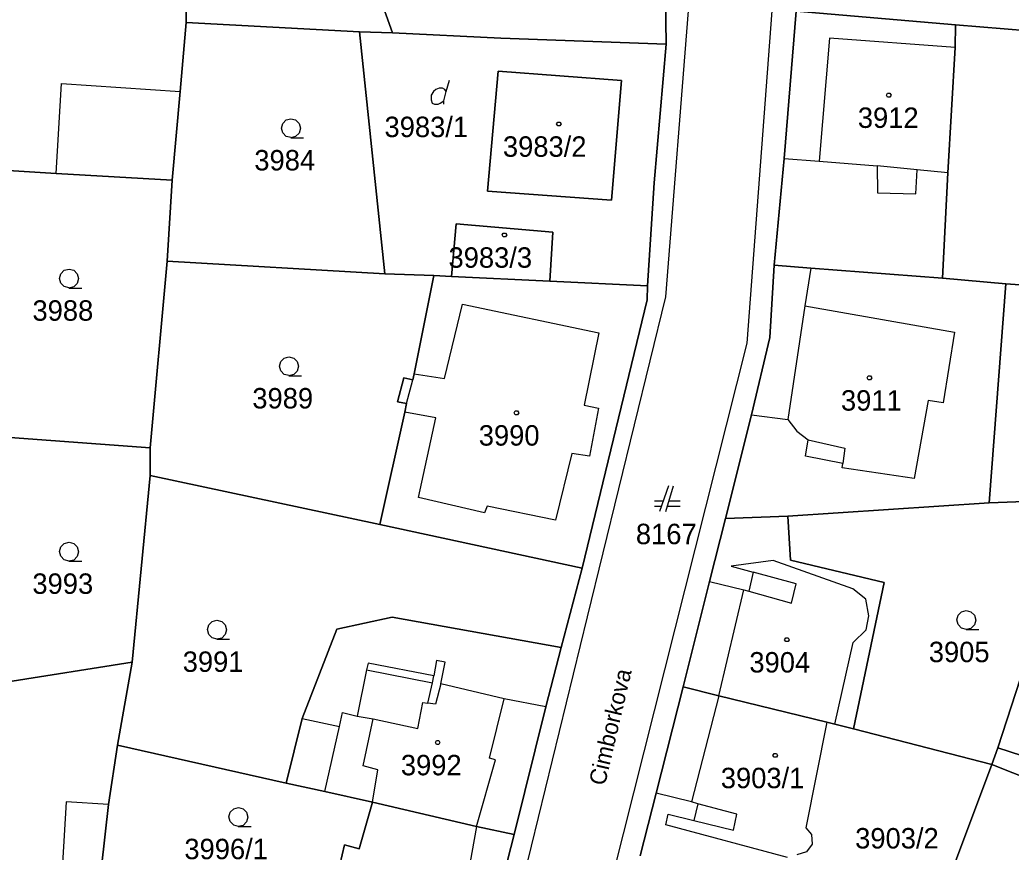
# Model space of a CAD drawing. Extents: x -263587 to -261993, y -1238795 to -1236748.
# Drawn here: x -262988.3 to -262910.7, y -1238143.7 to -1238078.5 of the extents above; entities that cross this region are included whole.
import ezdxf

# ---------------------------------------------------------------- set-up
doc = ezdxf.new("R2010")
doc.units = 0
doc.layers.add('Vrstva 1', color=7, linetype='Continuous')

msp = doc.modelspace()

# ---------------------------------------------------------------- linework, layer by layer
at = {"layer": 'Vrstva 1'}
for p, q in [((-262959.1, -1238079.5), (-262966.6, -1238058.58)), ((-262966.6, -1238058.58), (-262959.1, -1238079.5)), ((-262975.26, -1238076.52), (-262975.25, -1238078.69)), ((-262975.25, -1238078.69), (-262975.26, -1238076.52)), ((-262929.27, -1238076.08), (-262931.35, -1238103.82)), ((-262935.86, -1238076.77), (-262937.73, -1238100.17)), ((-262937.72, -1238076.78), (-262937.67, -1238080.39)), ((-262937.67, -1238080.39), (-262937.72, -1238076.78)), ((-262928.43, -1238089.35), (-262927.5, -1238077.82)), ((-262927.5, -1238077.82), (-262928.43, -1238089.35)), ((-262927.5, -1238077.82), (-262915, -1238078.87)), ((-262915, -1238078.87), (-262927.5, -1238077.82)), ((-262975.25, -1238078.69), (-262975.73, -1238084.11)), ((-262975.73, -1238084.11), (-262975.25, -1238078.69)), ((-262961.67, -1238079.42), (-262975.25, -1238078.69)), ((-262975.25, -1238078.69), (-262961.67, -1238079.42)), ((-262915, -1238078.87), (-262915.05, -1238080.66)), ((-262915.05, -1238080.66), (-262915, -1238078.87)), ((-262915, -1238078.87), (-262909.29, -1238079.36)), ((-262909.29, -1238079.36), (-262915, -1238078.87)), ((-262959.1, -1238079.5), (-262961.67, -1238079.42)), ((-262961.67, -1238079.42), (-262959.69, -1238098.38)), ((-262959.69, -1238098.38), (-262961.67, -1238079.42)), ((-262961.67, -1238079.42), (-262959.1, -1238079.5)), ((-262950.61, -1238079.92), (-262959.1, -1238079.5)), ((-262959.1, -1238079.5), (-262950.61, -1238079.92)), ((-262937.67, -1238080.39), (-262950.61, -1238079.92)), ((-262950.61, -1238079.92), (-262937.67, -1238080.39)), ((-262938.61, -1238091.24), (-262937.67, -1238080.39)), ((-262937.67, -1238080.39), (-262938.61, -1238091.24)), ((-262924.88, -1238079.92), (-262925.68, -1238089.56)), ((-262915.05, -1238080.66), (-262924.88, -1238079.92)), ((-262915.05, -1238080.66), (-262915.62, -1238090.47)), ((-262915.62, -1238090.47), (-262915.05, -1238080.66)), ((-262950.82, -1238082.51), (-262951.66, -1238091.9)), ((-262951.66, -1238091.9), (-262950.82, -1238082.51)), ((-262941.16, -1238083.23), (-262950.82, -1238082.51)), ((-262950.82, -1238082.51), (-262941.16, -1238083.23)), ((-262985.44, -1238090.51), (-262985, -1238083.47)), ((-262985, -1238083.47), (-262975.73, -1238084.11)), ((-262954.9, -1238084.11), (-262954.63, -1238083.21)), ((-262941.94, -1238092.6), (-262941.16, -1238083.23)), ((-262941.16, -1238083.23), (-262941.94, -1238092.6)), ((-262975.73, -1238084.11), (-262976.35, -1238091.04)), ((-262976.35, -1238091.04), (-262975.73, -1238084.11)), ((-262985.44, -1238090.51), (-263011.06, -1238089)), ((-263011.06, -1238089), (-262985.44, -1238090.51)), ((-262929.2, -1238097.69), (-262928.43, -1238089.35)), ((-262928.43, -1238089.35), (-262929.2, -1238097.69)), ((-262928.43, -1238089.35), (-262925.68, -1238089.56)), ((-262925.68, -1238089.56), (-262921.14, -1238089.92)), ((-262976.35, -1238091.04), (-262985.44, -1238090.51)), ((-262985.44, -1238090.51), (-262976.35, -1238091.04)), ((-262918.02, -1238090.23), (-262921.14, -1238089.92)), ((-262921.14, -1238089.92), (-262921.12, -1238092.03)), ((-262918.13, -1238092.12), (-262918.02, -1238090.23)), ((-262915.62, -1238090.47), (-262918.02, -1238090.23)), ((-262915.62, -1238090.47), (-262916.04, -1238098.72)), ((-262916.04, -1238098.72), (-262915.62, -1238090.47)), ((-262976.75, -1238097.38), (-262976.35, -1238091.04)), ((-262976.35, -1238091.04), (-262976.75, -1238097.38)), ((-262939.13, -1238099.33), (-262938.61, -1238091.24)), ((-262938.61, -1238091.24), (-262939.13, -1238099.33)), ((-262951.66, -1238091.9), (-262941.94, -1238092.6)), ((-262941.94, -1238092.6), (-262951.66, -1238091.9)), ((-262921.12, -1238092.03), (-262918.13, -1238092.12)), ((-262954.12, -1238094.47), (-262954.47, -1238098.59)), ((-262954.47, -1238098.59), (-262954.12, -1238094.47)), ((-262946.53, -1238095.12), (-262954.12, -1238094.47)), ((-262954.12, -1238094.47), (-262946.53, -1238095.12)), ((-262946.78, -1238098.96), (-262946.53, -1238095.12)), ((-262946.53, -1238095.12), (-262946.78, -1238098.96)), ((-262976.75, -1238097.38), (-262978.06, -1238112)), ((-262978.06, -1238112), (-262976.75, -1238097.38)), ((-262959.69, -1238098.38), (-262976.75, -1238097.38)), ((-262976.75, -1238097.38), (-262959.69, -1238098.38)), ((-262959.69, -1238098.38), (-262955.86, -1238098.52)), ((-262955.86, -1238098.52), (-262959.69, -1238098.38)), ((-262929.54, -1238103.37), (-262929.2, -1238097.69)), ((-262929.2, -1238097.69), (-262929.54, -1238103.37)), ((-262926.33, -1238097.93), (-262929.2, -1238097.69)), ((-262929.2, -1238097.69), (-262926.33, -1238097.93)), ((-262926.33, -1238097.93), (-262926.8, -1238100.88)), ((-262916.04, -1238098.72), (-262926.33, -1238097.93)), ((-262926.33, -1238097.93), (-262916.04, -1238098.72)), ((-262955.86, -1238098.52), (-262957.39, -1238106.22)), ((-262957.39, -1238106.22), (-262955.86, -1238098.52)), ((-262955.86, -1238098.52), (-262954.47, -1238098.59)), ((-262954.47, -1238098.59), (-262955.86, -1238098.52)), ((-262954.47, -1238098.59), (-262946.78, -1238098.96)), ((-262946.78, -1238098.96), (-262954.47, -1238098.59)), ((-262946.78, -1238098.96), (-262939.13, -1238099.33)), ((-262939.13, -1238099.33), (-262946.78, -1238098.96)), ((-262911.06, -1238099.15), (-262916.04, -1238098.72)), ((-262916.04, -1238098.72), (-262911.06, -1238099.15)), ((-262912.38, -1238116.3), (-262911.06, -1238099.15)), ((-262911.06, -1238099.15), (-262912.38, -1238116.3)), ((-262901.22, -1238099.95), (-262911.06, -1238099.15)), ((-262911.06, -1238099.15), (-262901.22, -1238099.95)), ((-262939.13, -1238099.33), (-262939.16, -1238100.42)), ((-262939.16, -1238100.42), (-262939.13, -1238099.33)), ((-262939.16, -1238100.42), (-262944.25, -1238121.44)), ((-262944.25, -1238121.44), (-262939.16, -1238100.42)), ((-262937.73, -1238100.17), (-262943.84, -1238125.24)), ((-262955.02, -1238106.58), (-262953.62, -1238100.76)), ((-262953.62, -1238100.76), (-262942.93, -1238102.99)), ((-262926.8, -1238100.88), (-262928.13, -1238109.79)), ((-262926.8, -1238100.88), (-262915.09, -1238102.94)), ((-262942.93, -1238102.99), (-262944.1, -1238108.65)), ((-262915.09, -1238102.94), (-262915.97, -1238108.49)), ((-262931.35, -1238103.82), (-262942.36, -1238147.46)), ((-262930.99, -1238109.43), (-262929.54, -1238103.37)), ((-262929.54, -1238103.37), (-262930.99, -1238109.43)), ((-262958.22, -1238106.51), (-262958.69, -1238108.39)), ((-262958.69, -1238108.39), (-262958.22, -1238106.51)), ((-262957.49, -1238106.68), (-262958.22, -1238106.51)), ((-262958.22, -1238106.51), (-262957.49, -1238106.68)), ((-262958, -1238108.54), (-262957.49, -1238106.68)), ((-262957.39, -1238106.22), (-262957.49, -1238106.68)), ((-262957.49, -1238106.68), (-262957.39, -1238106.22)), ((-262957.39, -1238106.22), (-262955.02, -1238106.58)), ((-262958.69, -1238108.39), (-262958, -1238108.54)), ((-262958, -1238108.54), (-262958.69, -1238108.39)), ((-262917.15, -1238108.29), (-262918.26, -1238114.41)), ((-262915.97, -1238108.49), (-262917.15, -1238108.29)), ((-262958.14, -1238109.2), (-262960.08, -1238118.02)), ((-262960.08, -1238118.02), (-262958.14, -1238109.2)), ((-262958, -1238108.54), (-262958.14, -1238109.2)), ((-262958.14, -1238109.2), (-262958, -1238108.54)), ((-262955.69, -1238109.65), (-262958.14, -1238109.2)), ((-262944.1, -1238108.65), (-262942.96, -1238108.9)), ((-262942.96, -1238108.9), (-262943.67, -1238112.66)), ((-262957.07, -1238115.9), (-262955.69, -1238109.65)), ((-262933.02, -1238117.55), (-262930.99, -1238109.43)), ((-262930.99, -1238109.43), (-262933.02, -1238117.55)), ((-262930.99, -1238109.43), (-262928.13, -1238109.79)), ((-262928.13, -1238109.79), (-262927.44, -1238110.7)), ((-262927.44, -1238110.7), (-262926.55, -1238111.38)), ((-262978.06, -1238112), (-262989.74, -1238111.14)), ((-262989.74, -1238111.14), (-262978.06, -1238112)), ((-262926.76, -1238112.66), (-262926.55, -1238111.38)), ((-262926.55, -1238111.38), (-262923.69, -1238112.02)), ((-262978.07, -1238114.16), (-262978.06, -1238112)), ((-262978.06, -1238112), (-262978.07, -1238114.16)), ((-262923.69, -1238112.02), (-262923.84, -1238113.23)), ((-262945.05, -1238112.45), (-262946.34, -1238117.66)), ((-262943.67, -1238112.66), (-262945.05, -1238112.45)), ((-262923.84, -1238113.23), (-262926.76, -1238112.66)), ((-262923.88, -1238113.56), (-262923.84, -1238113.23)), ((-262918.26, -1238114.41), (-262923.88, -1238113.56)), ((-262978.07, -1238114.16), (-262979.47, -1238128.79)), ((-262979.47, -1238128.79), (-262978.07, -1238114.16)), ((-262960.08, -1238118.02), (-262978.07, -1238114.16)), ((-262978.07, -1238114.16), (-262960.08, -1238118.02)), ((-262937.48, -1238114.98), (-262938.18, -1238116.98)), ((-262937.68, -1238116.98), (-262937.08, -1238114.98)), ((-262951.9, -1238117.1), (-262957.07, -1238115.9)), ((-262937.9, -1238116.18), (-262938.58, -1238116.18)), ((-262936.58, -1238116.18), (-262937.44, -1238116.18)), ((-262905.7, -1238116.06), (-262912.38, -1238116.3)), ((-262912.38, -1238116.3), (-262905.7, -1238116.06)), ((-262951.68, -1238116.56), (-262951.9, -1238117.1)), ((-262946.34, -1238117.66), (-262951.68, -1238116.56)), ((-262938.58, -1238116.58), (-262938.04, -1238116.58)), ((-262937.56, -1238116.58), (-262936.58, -1238116.58)), ((-262928.14, -1238117.35), (-262912.38, -1238116.3)), ((-262912.38, -1238116.3), (-262928.14, -1238117.35)), ((-262934.28, -1238122.46), (-262933.02, -1238117.55)), ((-262933.02, -1238117.55), (-262934.28, -1238122.46)), ((-262928.14, -1238117.35), (-262933.02, -1238117.55)), ((-262933.02, -1238117.55), (-262928.14, -1238117.35)), ((-262927.94, -1238120.79), (-262928.14, -1238117.35)), ((-262928.14, -1238117.35), (-262927.94, -1238120.79)), ((-262944.25, -1238121.44), (-262960.08, -1238118.02)), ((-262960.08, -1238118.02), (-262944.25, -1238121.44)), ((-262929.29, -1238120.82), (-262932.57, -1238121.28)), ((-262923.05, -1238123.04), (-262929.29, -1238120.82)), ((-262920.6, -1238122.56), (-262927.94, -1238120.79)), ((-262927.94, -1238120.79), (-262920.6, -1238122.56)), ((-262944.25, -1238121.44), (-262945.89, -1238127.64)), ((-262945.89, -1238127.64), (-262944.25, -1238121.44)), ((-262932.57, -1238121.28), (-262930.86, -1238121.74)), ((-262936.34, -1238130.73), (-262934.28, -1238122.46)), ((-262934.28, -1238122.46), (-262936.34, -1238130.73)), ((-262934.28, -1238122.46), (-262931.59, -1238123.12)), ((-262930.86, -1238121.74), (-262931.19, -1238123.22)), ((-262927.49, -1238122.65), (-262930.86, -1238121.74)), ((-262933.54, -1238131.42), (-262931.59, -1238123.12)), ((-262931.59, -1238123.12), (-262931.19, -1238123.22)), ((-262931.19, -1238123.22), (-262927.86, -1238124.18)), ((-262927.86, -1238124.18), (-262927.49, -1238122.65)), ((-262922.04, -1238123.86), (-262923.05, -1238123.04)), ((-262923.01, -1238134.01), (-262920.6, -1238122.56)), ((-262920.6, -1238122.56), (-262923.01, -1238134.01)), ((-262921.79, -1238125.16), (-262922.04, -1238123.86)), ((-262911.7, -1238135.5), (-262907.9, -1238123.78)), ((-262907.9, -1238123.78), (-262911.7, -1238135.5)), ((-262963.45, -1238126.21), (-262959.12, -1238125.26)), ((-262959.12, -1238125.26), (-262963.45, -1238126.21)), ((-262959.12, -1238125.26), (-262945.89, -1238127.64)), ((-262945.89, -1238127.64), (-262959.12, -1238125.26)), ((-262943.84, -1238125.24), (-262949.77, -1238149.44)), ((-262922.01, -1238126.27), (-262921.79, -1238125.16)), ((-262966.16, -1238133.2), (-262963.45, -1238126.21)), ((-262963.45, -1238126.21), (-262966.16, -1238133.2)), ((-262923.03, -1238127.25), (-262922.01, -1238126.27)), ((-262945.89, -1238127.64), (-262947.09, -1238132.29)), ((-262947.09, -1238132.29), (-262945.89, -1238127.64)), ((-262924.45, -1238133.64), (-262923.03, -1238127.25)), ((-262955.64, -1238128.67), (-262955.87, -1238129.87)), ((-262954.96, -1238128.8), (-262955.64, -1238128.67)), ((-262979.47, -1238128.79), (-262989.36, -1238130.35)), ((-262989.36, -1238130.35), (-262979.47, -1238128.79)), ((-262980.63, -1238135.28), (-262979.47, -1238128.79)), ((-262979.47, -1238128.79), (-262980.63, -1238135.28)), ((-262961.14, -1238129.38), (-262961.87, -1238133.01)), ((-262960.99, -1238128.88), (-262961.14, -1238129.38)), ((-262961.14, -1238129.38), (-262955.96, -1238130.41)), ((-262955.87, -1238129.87), (-262960.99, -1238128.88)), ((-262955.32, -1238130.48), (-262954.96, -1238128.8)), ((-262955.96, -1238130.41), (-262955.87, -1238129.87)), ((-262956.34, -1238131.99), (-262955.96, -1238130.41)), ((-262955.32, -1238130.48), (-262955.72, -1238132.07)), ((-262950.34, -1238131.66), (-262955.32, -1238130.48)), ((-262936.34, -1238130.73), (-262938.45, -1238139.06)), ((-262938.45, -1238139.06), (-262936.34, -1238130.73)), ((-262933.54, -1238131.42), (-262936.34, -1238130.73)), ((-262936.34, -1238130.73), (-262933.54, -1238131.42)), ((-262951.51, -1238136.3), (-262950.34, -1238131.66)), ((-262947.09, -1238132.29), (-262950.34, -1238131.66)), ((-262933.54, -1238131.42), (-262935.69, -1238139.73)), ((-262925.08, -1238133.5), (-262933.54, -1238131.42)), ((-262933.54, -1238131.42), (-262925.08, -1238133.5)), ((-262957.11, -1238133.99), (-262956.73, -1238131.94)), ((-262956.73, -1238131.94), (-262956.34, -1238131.99)), ((-262955.72, -1238132.07), (-262956.34, -1238131.99)), ((-262947.09, -1238132.29), (-262949.58, -1238142.28)), ((-262949.58, -1238142.28), (-262947.09, -1238132.29)), ((-262967.41, -1238138.26), (-262966.16, -1238133.2)), ((-262966.16, -1238133.2), (-262967.41, -1238138.26)), ((-262966.16, -1238133.2), (-262963.25, -1238133.82)), ((-262963.25, -1238133.82), (-262963.01, -1238132.73)), ((-262963.01, -1238132.73), (-262961.87, -1238133.01)), ((-262961.87, -1238133.01), (-262960.6, -1238133.24)), ((-262961.39, -1238136.9), (-262960.6, -1238133.24)), ((-262960.6, -1238133.24), (-262957.11, -1238133.99)), ((-262964.39, -1238138.93), (-262963.25, -1238133.82)), ((-262925.08, -1238133.5), (-262926.73, -1238141.76)), ((-262924.45, -1238133.64), (-262925.08, -1238133.5)), ((-262925.08, -1238133.5), (-262924.45, -1238133.64)), ((-262923.01, -1238134.01), (-262924.45, -1238133.64)), ((-262924.45, -1238133.64), (-262923.01, -1238134.01)), ((-262912.18, -1238136.81), (-262923.01, -1238134.01)), ((-262923.01, -1238134.01), (-262912.18, -1238136.81)), ((-262980.63, -1238135.28), (-262981.34, -1238139.94)), ((-262981.34, -1238139.94), (-262980.63, -1238135.28)), ((-262967.41, -1238138.26), (-262980.63, -1238135.28)), ((-262980.63, -1238135.28), (-262967.41, -1238138.26)), ((-262912.18, -1238136.81), (-262911.7, -1238135.5)), ((-262911.7, -1238135.5), (-262912.18, -1238136.81)), ((-262911.7, -1238135.5), (-262906.1, -1238137.3)), ((-262906.1, -1238137.3), (-262911.7, -1238135.5)), ((-262952.51, -1238141.66), (-262951.04, -1238136.43)), ((-262951.04, -1238136.43), (-262951.51, -1238136.3)), ((-262960.23, -1238137.22), (-262961.39, -1238136.9)), ((-262960.65, -1238139.76), (-262960.23, -1238137.22)), ((-262917.05, -1238149.82), (-262912.18, -1238136.81)), ((-262912.18, -1238136.81), (-262917.05, -1238149.82)), ((-262912.18, -1238136.81), (-262904.69, -1238139.75)), ((-262904.69, -1238139.75), (-262912.18, -1238136.81)), ((-262964.39, -1238138.93), (-262967.41, -1238138.26)), ((-262967.41, -1238138.26), (-262964.39, -1238138.93)), ((-262960.65, -1238139.76), (-262964.39, -1238138.93)), ((-262964.39, -1238138.93), (-262960.65, -1238139.76)), ((-262938.45, -1238139.06), (-262939.7, -1238143.96)), ((-262939.7, -1238143.96), (-262938.45, -1238139.06)), ((-262935.69, -1238139.73), (-262938.45, -1238139.06)), ((-262984.65, -1238139.73), (-262984.92, -1238144.55)), ((-262981.34, -1238139.94), (-262984.65, -1238139.73)), ((-262981.34, -1238139.94), (-262981.89, -1238144.81)), ((-262981.89, -1238144.81), (-262981.34, -1238139.94)), ((-262961.71, -1238143.42), (-262960.65, -1238139.76)), ((-262960.65, -1238139.76), (-262961.71, -1238143.42)), ((-262952.51, -1238141.66), (-262960.65, -1238139.76)), ((-262960.65, -1238139.76), (-262952.51, -1238141.66)), ((-262935.18, -1238139.89), (-262935.69, -1238139.73)), ((-262935.18, -1238139.89), (-262935.51, -1238141.19)), ((-262932.13, -1238140.69), (-262935.18, -1238139.89)), ((-262937.69, -1238141.52), (-262937.51, -1238140.69)), ((-262937.51, -1238140.69), (-262935.51, -1238141.19)), ((-262932.39, -1238141.94), (-262932.13, -1238140.69)), ((-262952.51, -1238141.66), (-262953.52, -1238147.28)), ((-262949.58, -1238142.28), (-262952.51, -1238141.66)), ((-262952.51, -1238141.66), (-262949.58, -1238142.28)), ((-262928.17, -1238144.09), (-262937.69, -1238141.52)), ((-262935.51, -1238141.19), (-262932.39, -1238141.94)), ((-262926.73, -1238141.76), (-262926.29, -1238142.29)), ((-262949.58, -1238142.28), (-262952.25, -1238152.94)), ((-262952.25, -1238152.94), (-262949.58, -1238142.28)), ((-262926.29, -1238142.29), (-262926.24, -1238143.04)), ((-262964.26, -1238149.07), (-262962.85, -1238143.1)), ((-262962.85, -1238143.1), (-262964.26, -1238149.07)), ((-262962.85, -1238143.1), (-262961.71, -1238143.42)), ((-262961.71, -1238143.42), (-262962.85, -1238143.1)), ((-262926.24, -1238143.04), (-262926.68, -1238143.64)), ((-262926.68, -1238143.64), (-262927.43, -1238143.88))]:
    msp.add_line(p, q, dxfattribs=at)
for points in [[(-262955.08, -1238085.1), (-262955.08, -1238084.83), (-262954.9, -1238084.11), (-262954.99, -1238083.93), (-262955.17, -1238083.84), (-262955.44, -1238083.84), (-262955.71, -1238083.93), (-262955.89, -1238084.11), (-262956.07, -1238084.38), (-262956.07, -1238084.74), (-262955.98, -1238085.01), (-262955.8, -1238085.1), (-262955.53, -1238085.1), (-262955.35, -1238085.01), (-262955.08, -1238084.83)], [(-262967.04, -1238087.71), (-262967.42, -1238087.61), (-262967.69, -1238087.34), (-262967.79, -1238086.97), (-262967.69, -1238086.6), (-262967.42, -1238086.33), (-262967.05, -1238086.23), (-262966.68, -1238086.33), (-262966.41, -1238086.6), (-262966.31, -1238086.98), (-262966.41, -1238087.36), (-262966.68, -1238087.63), (-262967.06, -1238087.73), (-262966.06, -1238087.73)], [(-262984.41, -1238099.48), (-262984.79, -1238099.38), (-262985.06, -1238099.11), (-262985.16, -1238098.74), (-262985.06, -1238098.37), (-262984.79, -1238098.1), (-262984.42, -1238098), (-262984.05, -1238098.1), (-262983.78, -1238098.37), (-262983.68, -1238098.75), (-262983.78, -1238099.13), (-262984.05, -1238099.4), (-262984.43, -1238099.5), (-262983.43, -1238099.5)], [(-262967.19, -1238106.35), (-262967.57, -1238106.25), (-262967.84, -1238105.98), (-262967.94, -1238105.61), (-262967.84, -1238105.24), (-262967.57, -1238104.97), (-262967.2, -1238104.87), (-262966.83, -1238104.97), (-262966.56, -1238105.24), (-262966.46, -1238105.62), (-262966.56, -1238106), (-262966.83, -1238106.27), (-262967.21, -1238106.37), (-262966.21, -1238106.37)], [(-262984.41, -1238120.87), (-262984.79, -1238120.77), (-262985.06, -1238120.5), (-262985.16, -1238120.13), (-262985.06, -1238119.76), (-262984.79, -1238119.49), (-262984.42, -1238119.39), (-262984.05, -1238119.49), (-262983.78, -1238119.76), (-262983.68, -1238120.14), (-262983.78, -1238120.52), (-262984.05, -1238120.79), (-262984.43, -1238120.89), (-262983.43, -1238120.89)], [(-262914.16, -1238126.22), (-262914.54, -1238126.12), (-262914.81, -1238125.85), (-262914.91, -1238125.48), (-262914.81, -1238125.11), (-262914.54, -1238124.84), (-262914.17, -1238124.74), (-262913.8, -1238124.84), (-262913.53, -1238125.11), (-262913.43, -1238125.49), (-262913.53, -1238125.87), (-262913.8, -1238126.14), (-262914.18, -1238126.24), (-262913.18, -1238126.24)], [(-262972.83, -1238126.98), (-262973.21, -1238126.88), (-262973.48, -1238126.61), (-262973.58, -1238126.24), (-262973.48, -1238125.87), (-262973.21, -1238125.6), (-262972.84, -1238125.5), (-262972.47, -1238125.6), (-262972.2, -1238125.87), (-262972.1, -1238126.25), (-262972.2, -1238126.63), (-262972.47, -1238126.9), (-262972.85, -1238127), (-262971.85, -1238127)], [(-262971.15, -1238141.65), (-262971.53, -1238141.55), (-262971.8, -1238141.28), (-262971.9, -1238140.91), (-262971.8, -1238140.54), (-262971.53, -1238140.27), (-262971.16, -1238140.17), (-262970.79, -1238140.27), (-262970.52, -1238140.54), (-262970.42, -1238140.92), (-262970.52, -1238141.3), (-262970.79, -1238141.57), (-262971.17, -1238141.67), (-262970.17, -1238141.67)]]:
    msp.add_lwpolyline(points, dxfattribs=at)
for points in [[(-262920.15, -1238084.23), (-262920.06, -1238084.38), (-262920.15, -1238084.53), (-262920.33, -1238084.53), (-262920.42, -1238084.38), (-262920.33, -1238084.23)], [(-262945.98, -1238086.49), (-262945.89, -1238086.64), (-262945.98, -1238086.79), (-262946.16, -1238086.79), (-262946.25, -1238086.64), (-262946.16, -1238086.49)], [(-262950.24, -1238095.18), (-262950.15, -1238095.33), (-262950.24, -1238095.48), (-262950.42, -1238095.48), (-262950.51, -1238095.33), (-262950.42, -1238095.18)], [(-262921.66, -1238106.37), (-262921.57, -1238106.52), (-262921.66, -1238106.67), (-262921.84, -1238106.67), (-262921.93, -1238106.52), (-262921.84, -1238106.37)], [(-262949.3, -1238109.11), (-262949.21, -1238109.26), (-262949.3, -1238109.41), (-262949.48, -1238109.41), (-262949.57, -1238109.26), (-262949.48, -1238109.11)], [(-262928.12, -1238126.88), (-262928.03, -1238127.03), (-262928.12, -1238127.18), (-262928.3, -1238127.18), (-262928.39, -1238127.03), (-262928.3, -1238126.88)], [(-262955.47, -1238134.93), (-262955.38, -1238135.08), (-262955.47, -1238135.23), (-262955.65, -1238135.23), (-262955.74, -1238135.08), (-262955.65, -1238134.93)], [(-262929.04, -1238135.94), (-262928.95, -1238136.09), (-262929.04, -1238136.24), (-262929.22, -1238136.24), (-262929.31, -1238136.09), (-262929.22, -1238135.94)]]:
    msp.add_lwpolyline(points, close=True, dxfattribs=at)

# ---------------------------------------------------------------- texts
for s, p in [('3983/1', (-262959.72, -1238087.67)), ('3912', (-262922.66, -1238086.95)), ('3983/2', (-262950.449, -1238089.21)), ('3984', (-262969.914, -1238090.28)), ('3983/3', (-262954.709, -1238097.9)), ('3988', (-262987.284, -1238102.05)), ('3989', (-262970.07, -1238108.92)), ('3911', (-262923.981, -1238109.09)), ('3990', (-262952.34, -1238111.83)), ('8167', (-262940.038, -1238119.55)), ('3993', (-262987.29, -1238123.44)), ('3905', (-262917.103, -1238128.79)), ('3991', (-262975.521, -1238129.55)), ('3904', (-262931.153, -1238129.6)), ('3992', (-262958.44, -1238137.65)), ('3903/1', (-262933.39, -1238138.66)), ('3903/2', (-262922.869, -1238143.38)), ('3996/1', (-262975.391, -1238144.22))]:
    msp.add_text(s, height=1.6, dxfattribs=at).set_placement(p)
msp.add_text('Cimborkova', height=1.3, rotation=76.89094, dxfattribs=at).set_placement((-262942.466, -1238138.521))

doc.saveas('drawing.dxf')
